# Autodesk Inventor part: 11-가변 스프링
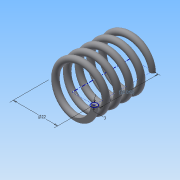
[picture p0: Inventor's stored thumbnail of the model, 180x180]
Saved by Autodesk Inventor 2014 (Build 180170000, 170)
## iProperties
Created: 2015-09
Part Number: 11-가변 스프링
Material: 강철, 탄소
Document SubType Name: Modeling
Designer: study
Density: 7.87 g/cm^3
Appearance: 반연마
Mass: 18.7976 g
Surface Area: 32.4648 cm^2
Volume: 2.38851 cm^3
Author: study
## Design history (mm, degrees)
sketch "스케치1"
  geometry: L1 (0, 0)-(11, 0); L2 (11, 0)-(11, 29.043); L3 (11, 29.043)-(0, 29.043); L4 (0, 29.043)-(0, 0); C1 r 1.5 at (11, 0)
  constraints: 8 end point, 2 parallel, 1 centre point, 1 coincident, 1 horizontal, 1 perpendicular
  dimensions: "d0" = 22 diameter of L2 L4; "d1" = 29.04259 distance of L1.end L2.end (derived); "d2" = 3 diameter of C1
feature "코일1" sketch "스케치1" pitch "d3" = 10; turns "d5" = 5; dims "d4" = 29.04259 (= d1), "d6" = 0, angle "d7" = 90 deg, angle "d8" = 90 deg, "d9" = 0, "d10" = 0
node "작업 평면1"
sketch "스케치2"
  geometry: L1 (-12.5, 0)-(-9.5, 0) reference; L2 (-12.5, 0)-(-9.5, 0) reference; 1 further point
  constraints: 2 horizontal alignment
extrude "돌출1" cut sketch "스케치2" stored distance "d12" = 10; taper "d13" = 0 deg
node "작업 평면2"
sketch "스케치3"
  geometry: L1 (-9.5, 0)-(-12.5, 0) reference; 1 further point
  constraints: 1 horizontal alignment
extrude "돌출2" cut sketch "스케치3" stored distance "d15" = 10; taper "d16" = 0 deg
node "솔리드1"
node "절단 모서리 투영1"
node "절단 모서리 투영2"
node "절단 모서리 투영3"
other parameters: "d11" = 0, "d14" = 29.04259 (= d1)
